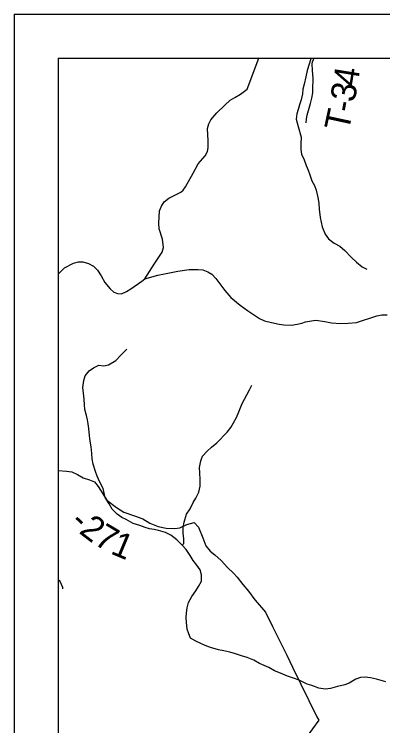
# Model space of a CAD drawing. Extents: x 0 to 34, y 0 to 22.
# Drawn here: x 2 to 2.84, y 19.381 to 21 of the extents above; entities that cross this region are included whole.
import ezdxf

# ---------------------------------------------------------------- set-up
doc = ezdxf.new("R2010")
doc.units = 0
for name, color, linetype in [('GM_X_County_Road', 7, 'Continuous'), ('GM_X_Minor_River', 7, 'Continuous'), ('GM_X_Township_Road', 7, 'Continuous'), ('GM_X_Township_Road_Text', 7, 'Continuous'), ('SH_Data', 7, 'Continuous')]:
    doc.layers.add(name, color=color, linetype=linetype)

msp = doc.modelspace()

# ---------------------------------------------------------------- linework, layer by layer
at = {"layer": 'GM_X_County_Road'}
msp.add_lwpolyline([(2.1107, 19.6926), (2.1105, 19.6955), (2.1049, 19.7092), (2.1, 19.7134)], dxfattribs=at)
at = {"layer": 'GM_X_Minor_River'}
for points in [[(2.6767, 20.9), (2.676, 20.8983), (2.6673, 20.8721), (2.6643, 20.8577), (2.6609, 20.841), (2.6579, 20.8293), (2.6567, 20.8186), (2.6541, 20.805), (2.6503, 20.794), (2.6469, 20.7834), (2.6439, 20.7731), (2.6427, 20.761), (2.6473, 20.7447), (2.654, 20.7204), (2.6533, 20.7045), (2.6533, 20.692), (2.6548, 20.6813), (2.6605, 20.6684), (2.665, 20.6556), (2.6695, 20.6449), (2.6733, 20.6347), (2.6782, 20.6211), (2.6839, 20.6101), (2.688, 20.5994), (2.6918, 20.5831), (2.6937, 20.5699), (2.6948, 20.5562), (2.6967, 20.5376), (2.7013, 20.516), (2.7081, 20.4997), (2.7164, 20.4891), (2.7292, 20.4792), (2.7417, 20.4724), (2.753, 20.4622), (2.7674, 20.4474), (2.7799, 20.436), (2.7927, 20.4254), (2.8033, 20.4197)], [(2.2045, 20.2001), (2.2151, 20.2024), (2.2317, 20.2119), (2.2427, 20.2244), (2.2566, 20.2377)], [(2.8469, 19.481), (2.8364, 19.484), (2.8254, 19.4871), (2.8114, 19.4905), (2.7993, 19.492), (2.7891, 19.4912), (2.7781, 19.487), (2.7634, 19.4779), (2.7536, 19.4745), (2.7366, 19.4707), (2.7207, 19.4658), (2.7082, 19.4646), (2.6942, 19.4669), (2.678, 19.4726), (2.6674, 19.4763), (2.6489, 19.4851), (2.6364, 19.4892), (2.6224, 19.4945), (2.6069, 19.5006), (2.5933, 19.5059), (2.5801, 19.5135), (2.5585, 19.5229), (2.5461, 19.5305), (2.5306, 19.5366), (2.5181, 19.5407), (2.5041, 19.5449), (2.4909, 19.5491), (2.4773, 19.5517), (2.4655, 19.554), (2.4474, 19.5593), (2.4353, 19.5638), (2.4251, 19.5687), (2.4141, 19.5737), (2.402, 19.5809), (2.3975, 19.5907), (2.3941, 19.601), (2.3922, 19.6173), (2.3918, 19.6268), (2.3922, 19.6381), (2.3937, 19.6495), (2.3971, 19.6617), (2.4047, 19.6753), (2.4138, 19.6882), (2.4202, 19.6981), (2.427, 19.7106), (2.427, 19.7243), (2.424, 19.736), (2.4161, 19.747), (2.4078, 19.7572), (2.4006, 19.769), (2.3919, 19.7823), (2.3828, 19.7925), (2.3707, 19.8039), (2.3571, 19.8152), (2.3446, 19.8209), (2.3291, 19.8255), (2.3189, 19.8281), (2.3083, 19.8296), (2.2985, 19.8323), (2.2864, 19.8368), (2.2713, 19.8417), (2.2551, 19.8505), (2.2452, 19.8554), (2.2346, 19.8626), (2.2229, 19.874), (2.2161, 19.8865), (2.2071, 19.9005), (2.2029, 19.9214), (2.1953, 19.9358), (2.1889, 19.9494), (2.1851, 19.96), (2.1802, 19.9763), (2.1776, 19.9885), (2.1768, 20.001), (2.1753, 20.0158), (2.1734, 20.0291), (2.1719, 20.0416), (2.17, 20.0575), (2.1685, 20.0681), (2.1666, 20.0776), (2.1648, 20.0875), (2.161, 20.1007), (2.1602, 20.1113), (2.1595, 20.1246), (2.1576, 20.1379), (2.1561, 20.1508), (2.1587, 20.1671), (2.1614, 20.1777), (2.1704, 20.1887), (2.1807, 20.1959), (2.1928, 20.2016), (2.2045, 20.2001)], [(2.3828, 19.7925), (2.3866, 19.7959), (2.3866, 19.8069), (2.3847, 19.8194), (2.3851, 19.8327), (2.387, 19.8445), (2.3927, 19.8623), (2.4006, 19.8748), (2.4078, 19.8892), (2.4138, 19.8987), (2.4203, 19.9124), (2.424, 19.926), (2.4237, 19.9412), (2.4229, 19.9568), (2.4225, 19.9685), (2.4252, 19.9837), (2.4286, 19.9947), (2.4396, 20.0061), (2.4494, 20.0152), (2.4615, 20.0251), (2.4853, 20.049), (2.4932, 20.0596), (2.4997, 20.0706), (2.5061, 20.0824), (2.5118, 20.0956), (2.5197, 20.1146), (2.525, 20.1245), (2.5299, 20.1343), (2.5364, 20.1453), (2.5417, 20.156)]]:
    msp.add_lwpolyline(points, dxfattribs=at)
at = {"layer": 'GM_X_Township_Road'}
msp.add_line((2.6349, 19.5133), (2.6897, 19.4018), dxfattribs=at)
for points in [[(2.2979, 20.3977), (2.3189, 20.4315), (2.3371, 20.4586), (2.34, 20.4691), (2.3378, 20.4882), (2.3302, 20.512), (2.3295, 20.525), (2.3313, 20.5524), (2.3356, 20.5632), (2.3414, 20.5733), (2.3522, 20.5813), (2.3799, 20.5949), (2.3851, 20.5996), (2.3899, 20.6074), (2.4074, 20.6386), (2.4193, 20.6595), (2.4351, 20.6775), (2.4406, 20.688), (2.4416, 20.6959), (2.4417, 20.7119), (2.4405, 20.7398), (2.4431, 20.7507), (2.4482, 20.7595), (2.4616, 20.7758), (2.4799, 20.7934), (2.4919, 20.8043), (2.5027, 20.8106), (2.5152, 20.818), (2.5308, 20.8299), (2.5574, 20.9)], [(2.6648, 20.7526), (2.6659, 20.762), (2.6678, 20.7701), (2.6689, 20.776), (2.6751, 20.7967), (2.6779, 20.8092), (2.68, 20.8211), (2.6802, 20.8298), (2.6808, 20.8535), (2.6793, 20.873), (2.6789, 20.8865), (2.6798, 20.8919), (2.6817, 20.8967), (2.6835, 20.9)], [(2.1, 20.4087), (2.1001, 20.4088), (2.1149, 20.4228), (2.1347, 20.4338), (2.1464, 20.4368), (2.1563, 20.4368), (2.1696, 20.4333), (2.1808, 20.4266), (2.1897, 20.4177), (2.1978, 20.4048), (2.2067, 20.39), (2.2187, 20.3755), (2.2266, 20.3676), (2.2357, 20.3643), (2.2441, 20.3638), (2.2561, 20.3689), (2.2659, 20.3754), (2.2909, 20.3931), (2.2979, 20.3977), (2.3271, 20.4067), (2.3725, 20.4157), (2.3983, 20.419), (2.419, 20.419), (2.4296, 20.4187), (2.4413, 20.4143), (2.45, 20.4089), (2.4595, 20.399), (2.4797, 20.3712), (2.4938, 20.3554), (2.515, 20.338), (2.5314, 20.326), (2.5586, 20.3081), (2.5703, 20.3024), (2.5859, 20.2987), (2.6035, 20.2947), (2.6139, 20.2934), (2.632, 20.293), (2.6447, 20.2946), (2.6551, 20.2974), (2.664, 20.3002), (2.6725, 20.3019), (2.682, 20.3035), (2.6874, 20.3037), (2.7079, 20.3009), (2.7227, 20.2983), (2.7435, 20.2964), (2.7611, 20.297), (2.7796, 20.2986), (2.8265, 20.3135), (2.8374, 20.3162), (2.8496, 20.316)], [(2.1, 19.9623), (2.1191, 19.9604), (2.1313, 19.9589), (2.144, 19.9527), (2.157, 19.9451), (2.1712, 19.9409), (2.1831, 19.9366), (2.1915, 19.9255), (2.2108, 19.8946), (2.2327, 19.8781), (2.2497, 19.8674), (2.2739, 19.8589), (2.2928, 19.8523), (2.3091, 19.8424), (2.328, 19.8347), (2.3465, 19.8311), (2.3659, 19.8299), (2.3772, 19.8313), (2.3932, 19.8388), (2.4099, 19.8436), (2.4197, 19.833), (2.4298, 19.809), (2.4365, 19.7903), (2.4463, 19.7785), (2.4569, 19.7704), (2.4712, 19.7574), (2.4859, 19.741), (2.4998, 19.7284), (2.5077, 19.7196), (2.5209, 19.7025), (2.5341, 19.6876), (2.5484, 19.6681), (2.549, 19.6674), (2.5728, 19.6395), (2.5888, 19.6069), (2.6014, 19.5813), (2.6209, 19.5417), (2.6349, 19.5133)], [(2.6897, 19.4018), (2.6937, 19.3937), (2.6653, 19.3545), (2.5886, 19.3171), (2.5654, 19.2909), (2.5551, 19.269), (2.5548, 19.2559), (2.5672, 19.2485), (2.5795, 19.2478), (2.5888, 19.2478), (2.602, 19.2486), (2.6102, 19.2504), (2.6192, 19.251), (2.6303, 19.251), (2.6329, 19.2514)]]:
    msp.add_lwpolyline(points, dxfattribs=at)
at = {"layer": 'SH_Data'}
for p, q in [((2, 21), (9, 21)), ((2, 21), (2, 14)), ((2.1, 20.9), (2.1, 14.1)), ((2.1, 20.9), (8.9, 20.9))]:
    msp.add_line(p, q, dxfattribs=at)

# ---------------------------------------------------------------- texts
at = {"layer": 'GM_X_Township_Road_Text'}
for s, rotation, p in [('4', 80.8357, (2.7816, 20.8334)), ('3', 80.115, (2.7754, 20.7981)), ('-', 79.3361, (2.771, 20.7743)), ('T', 77.7924, (2.7616, 20.7312)), ('-', 317.1587, (2.1241, 19.8407)), ('2', 322.4255, (2.1455, 19.8211)), ('7', 329.2123, (2.1793, 19.7957)), ('1', 337.3284, (2.2172, 19.7738))]:
    msp.add_text(s, height=0.0568, rotation=rotation, dxfattribs=at).set_placement(p)

doc.saveas('drawing.dxf')
